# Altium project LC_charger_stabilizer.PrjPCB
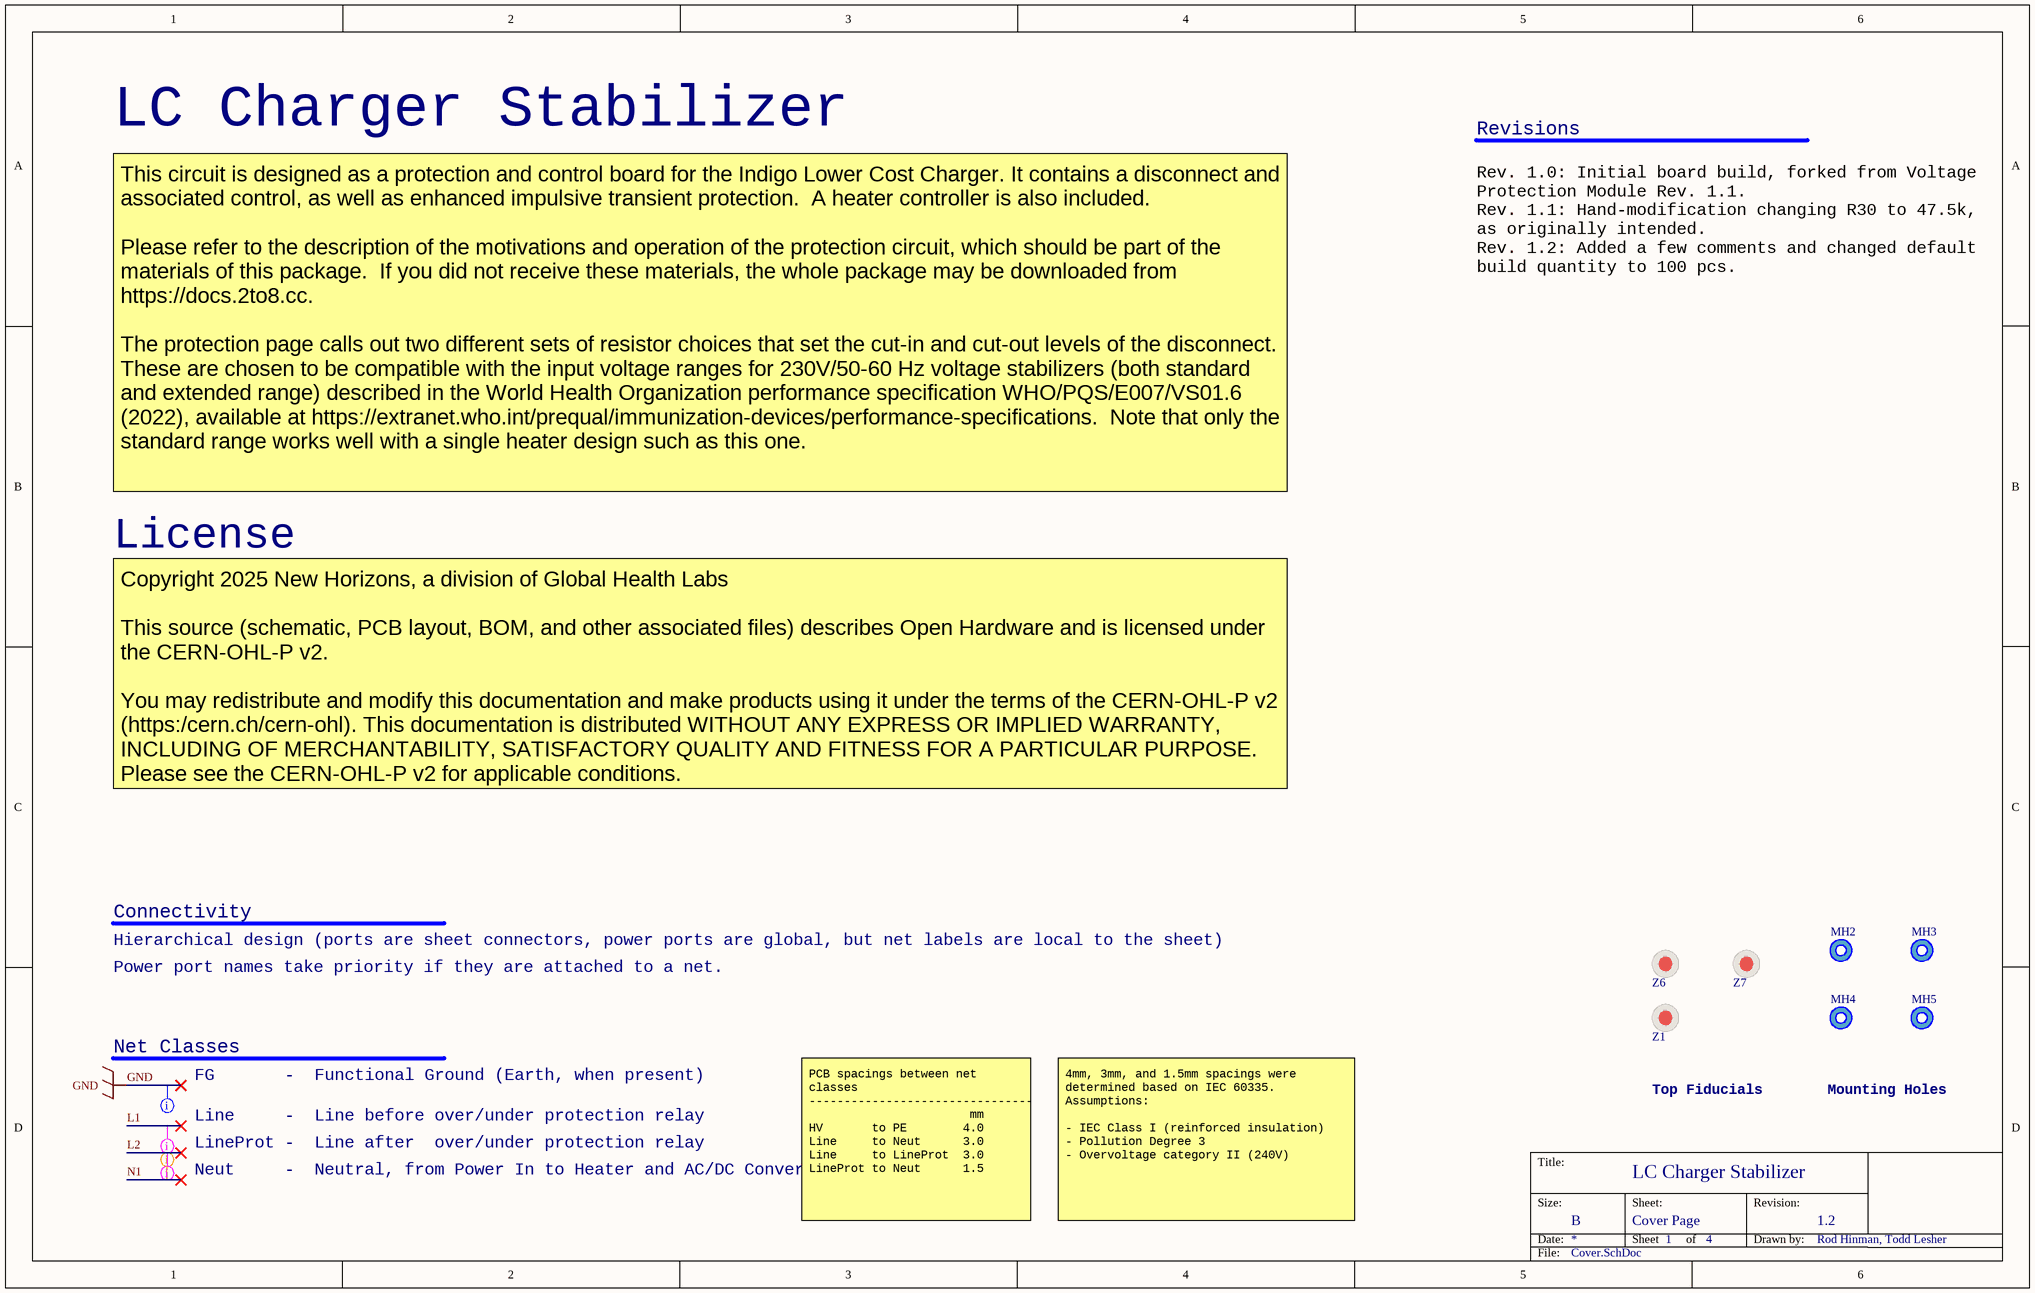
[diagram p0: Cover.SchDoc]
nhToday: 2025-07-28; nhSheetTotal: 4; nhProjRev: 1.2; nhProjName: LC Charger Stabilizer; nhEngPhone: 808-989-0977; nhEngName: Rod Hinman, Todd Lesher; nhEngEmail: rhinman@nhgh.org, rod@auroraresearch.com
5 sheets, 160 parts. Net scope: flat (ports and power ports of the same name join across sheets).
Board file: lc_charger_stab.PcbDoc
Sheets:
  Cover.SchDoc
  PowerHV.SchDoc
  Protect.SchDoc
  HeaterControl.SchDoc
  DebugProbe.SchDoc

## Sheet Cover.SchDoc
size B; SheetNumber: 1; SheetTotal: 4; nhSheetName: Cover Page

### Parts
MH2  MOUNTING_HOLE_3MM_UNPLATED  [MOUNT_HOLE_3MM_NOCOPPER]  (value not drawn)  (no BOM)
MH3  MOUNTING_HOLE_3MM_UNPLATED  [MOUNT_HOLE_3MM_NOCOPPER]  (value not drawn)  (no BOM)
MH4  MOUNTING_HOLE_3MM_UNPLATED  [MOUNT_HOLE_3MM_NOCOPPER]  (value not drawn)  (no BOM)
MH5  MOUNTING_HOLE_3MM_UNPLATED  [MOUNT_HOLE_3MM_NOCOPPER]  (value not drawn)  (no BOM)
Z1  FIDUCIAL_1_3  [FIDUCIAL_1_3_KEEPOUT]  (value not drawn)  (no BOM)
Z6  FIDUCIAL_1_3  [FIDUCIAL_1_3_KEEPOUT]  (value not drawn)  (no BOM)
Z7  FIDUCIAL_1_3  [FIDUCIAL_1_3_KEEPOUT]  (value not drawn)  (no BOM)

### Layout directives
net class Neut: N1
net class Line: L1
net class LineProt: L2
net class FG: GND

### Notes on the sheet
- LC Charger Stabilizer
- Revisions
- Rev. 1.0: Initial board build, forked from Voltage Protection Module Rev. 1.1.
  Rev. 1.1: Hand-modification changing R30 to 47.5k, as originally intended.
  Rev. 1.2: Added a few comments and changed default build quantity to 100 pcs.
- This circuit is designed as a protection and control board for the Indigo Lower Cost Charger. It contains a disconnect and associated control, as well as enhanced impulsive transient protection.  A heater controller is also included.
  Please refer to the description of the motivations and operation of the protection circuit, which should be part of the materials of this package.  If you did not receive these materials, the whole package may be downloaded from https://docs.2to8.cc.
  The protection page calls out two different sets of resistor choices that set the cut-in and cut-out levels of the disconnect.  These are chosen to be compatible with the input voltage ranges for 230V/50-60 Hz voltage stabilizers (both standard and extended range) described in the World Health Organization performance specification WHO/PQS/E007/VS01.6 (2022), available at https://extranet.who.int/prequal/immunization-devices/performance-specifications.  Note that only the standard range works well with a single heater design such as this one.
- License
- Copyright 2025 New Horizons, a division of Global Health Labs
  This source (schematic, PCB layout, BOM, and other associated files) describes Open Hardware and is licensed under the CERN-OHL-P v2.
  You may redistribute and modify this documentation and make products using it under the terms of the CERN-OHL-P v2 (https:/cern.ch/cern-ohl). This documentation is distributed WITHOUT ANY EXPRESS OR IMPLIED WARRANTY, INCLUDING OF MERCHANTABILITY, SATISFACTORY QUALITY AND FITNESS FOR A PARTICULAR PURPOSE. Please see the CERN-OHL-P v2 for applicable conditions.
- Hierarchical design (ports are sheet connectors, power ports are global, but net labels are local to the sheet)
- Power port names take priority if they are attached to a net.
- Connectivity
- Net Classes
- FG       -  Functional Ground (Earth, when present)
- Top Fiducials
- Mounting Holes
- Neut     -  Neutral, from Power In to Heater and AC/DC Converter
- Line     -  Line before over/under protection relay
- LineProt -  Line after  over/under protection relay
- PCB spacings between net classes
  --------------------------------
  mm
  HV       to PE        4.0
  Line     to Neut      3.0
  Line     to LineProt  3.0
  LineProt to Neut      1.5
- 4mm, 3mm, and 1.5mm spacings were determined based on IEC 60335.
  Assumptions:
  - IEC Class I (reinforced insulation)
  - Pollution Degree 3
  - Overvoltage category II (240V)

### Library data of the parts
MH2-MH5 = CMP-NOBOM-00004-3: Hole for M3 screw, unplated
Z1 Z6 Z7 = CMP-NOBOM-00000-13: Fiducial 1 mm copper, 3 mm solder mask, two footprint options.

## Sheet PowerHV.SchDoc
size B; SheetNumber: 2; SheetTotal: 4; nhSheetName: HV Power
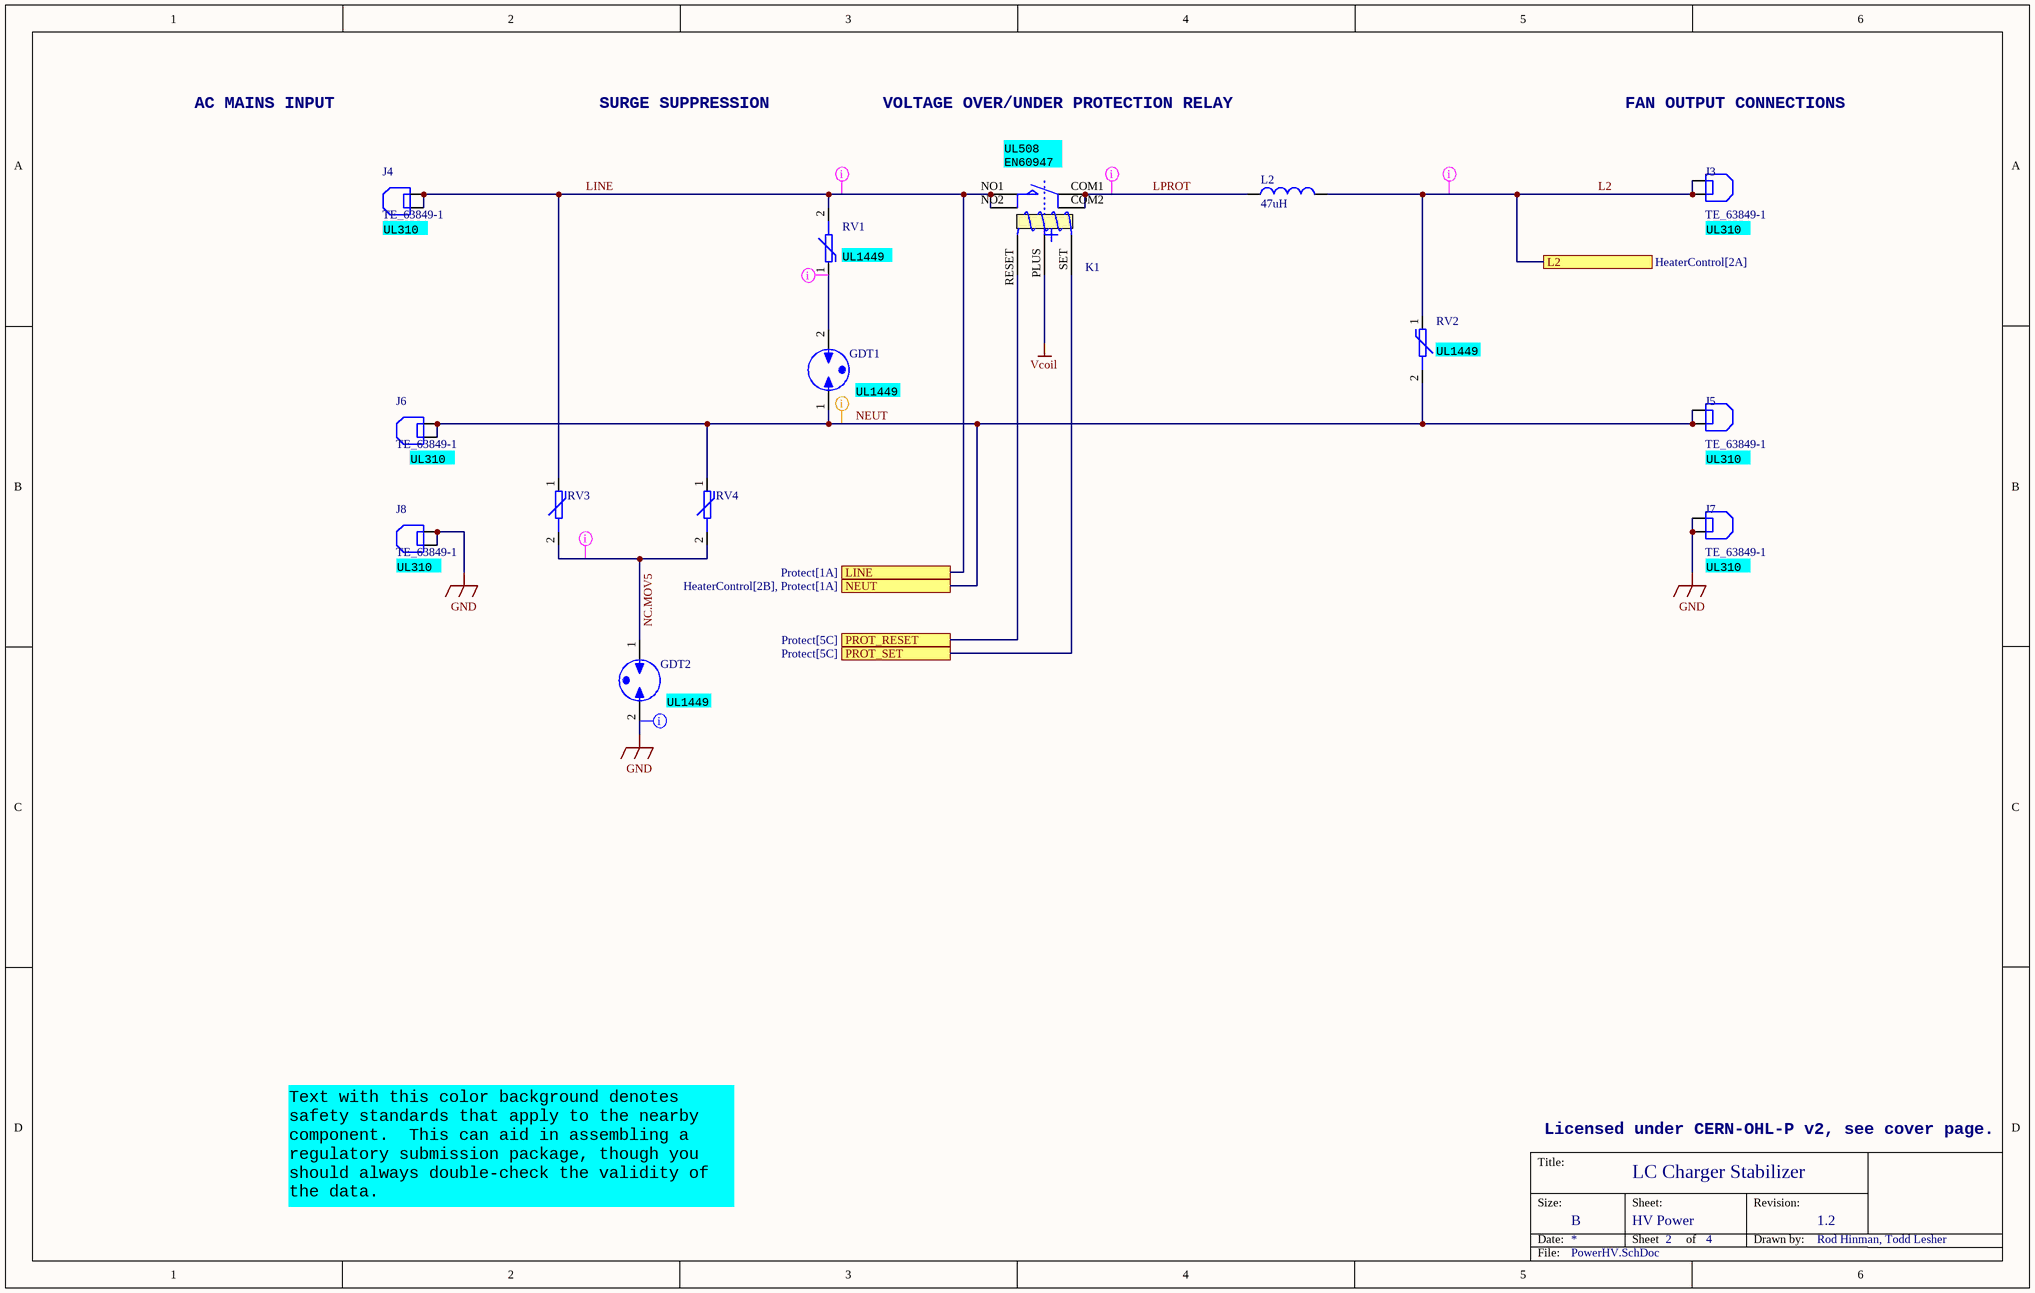
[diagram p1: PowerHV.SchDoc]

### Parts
GDT1  CG31.0L  [LITTELFUSE_CG3x]  (value not drawn)
GDT2  CG32.5L  [LITTELFUSE_CG3x]  (value not drawn)
J3  TE_63849-1  [AMP_63849-1]
J4  TE_63849-1  [AMP_63849-1]
J5  TE_63849-1  [AMP_63849-1]
J6  TE_63849-1  [AMP_63849-1]
J7  TE_63849-1  [AMP_63849-1]
J8  TE_63849-1  [AMP_63849-1]
K1  TE_CONN_2-1415898-5  [TE_RT1_2COIL_LATCHING]  (value not drawn)
L2  value 47uH  [BELFUSE_HCTI_TOROIDAL_INDUCTOR]  (hidden comment: BELFUSE_HCTI-47-10.7)
RV1  TMOV20RP300E  [MOV_RAD7.5P5.5S_DISC_20X11.5]  (value not drawn)
RV2  TMOV20RP300E  [MOV_RAD7.5P5.5S_DISC_20X11.5]  (value not drawn)
RV3  TMOV20RP300E  [MOV_RAD7.5P5.5S_DISC_20X11.5]  (value not drawn)
RV4  TMOV20RP300E  [MOV_RAD7.5P5.5S_DISC_20X11.5]  (value not drawn)

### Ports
L2 (see HeaterControl[2A]), LINE (see Protect[1A]), NEUT (see HeaterControl[2B], Protect[1A]), PROT_RESET (see Protect[5C]), PROT_SET (see Protect[5C])

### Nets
GND: GDT2.2 J7.1 J7.2 J8.1 J8.2
Vcoil: K1.PLUS
L2: J3.1 J3.2 L2.2 RV2.1 ; port L2
LINE: J4.1 J4.2 K1.NO1 K1.NO2 RV1.2 RV3.1 ; port LINE
LPROT: K1.COM1 K1.COM2 L2.1
NC.MOV5: GDT2.1 RV3.2 RV4.2
NEUT: GDT1.1 J5.1 J5.2 J6.1 J6.2 RV2.2 RV4.1 ; port NEUT
PROT_RESET: K1.RESET ; port PROT_RESET
PROT_SET: K1.SET ; port PROT_SET
NetGDT1_2: GDT1.2 RV1.1

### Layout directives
net class Line: LINE, NC.MOV5, NetGDT1_2
net class LineProt: L2, LPROT
net class Neut: NEUT
net class FG: GND

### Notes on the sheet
- AC MAINS INPUT
- SURGE SUPPRESSION
- VOLTAGE OVER/UNDER PROTECTION RELAY
- (near K1) UL508
  EN60947
- FAN OUTPUT CONNECTIONS
- (near J4) UL310
- (near J3) UL310
- (near RV1) UL1449
- (near RV2) UL1449
- (near GDT1) UL1449
- (near J6) UL310
- (near J5) UL310
- (near J8) UL310
- (near J7) UL310
- (near GDT2) UL1449
- Licensed under CERN-OHL-P v2, see cover page.
- Text with this color background denotes safety standards that apply to the nearby component.  This can aid in assembling a regulatory submission package, though you should always double-check the validity of the data.

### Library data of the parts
GDT1 = CMP-PROT-00004-3: CG3 Series - Two Terminal High Voltage Gas Plasma Arresters, 1000V, 10kA, plug in, RoHS; Breakdown Voltage: 1.0kV
GDT2 = CMP-PROT-00003-4: Arrestor; 2500 V (min.) (breakdown); Rugged Ceramic-metal Package; 1 Pf (max.); Breakdown Voltage: 2.5kV
J3-J8 = CMP-CONN-00004-5: Quick Disconnect Terminal 12-24AWG Brass Tab 14.02mm Tin Over Copper/Tin Over Nickel Bag; Tab Width: 6.35mm
K1 = CMP-RELAY-00000-5: Electromechanical Relay SPST-NO 16A 12VDC 240Ohm Through Hole; Contact Voltage Rating (AC): 250V; Coil Power: 600mW; Throw Configuration: SPST
L2 = CMP-IND-00005-4: 47 µH Shielded Toroidal Inductor 10.7 A 16mOhm Max Radial, Vertical (Open); Tolerance: 15%; DC Resistance (DCR): 16mR; Core Material: Ferrite; Current Rating: 10.7A
RV1 RV3 RV4 = CMP-PROT-00005-4: Thermally Protected Varistor 300 V RMS 775 V Clamp 10000 A 800 pF Radial Lead; Voltage Rating (AC): 300V; Varistor Voltage: 517V
RV2 = CMP-PROT-00005-4: Thermally Protected Varistor 300 V RMS 775 V Clamp 10000 A 800 pF Radial Lead; Varistor Voltage: 517V; Voltage Rating (AC): 300V

## Sheet Protect.SchDoc
size B; SheetNumber: 3; SheetTotal: 4; nhSheetName: Protect
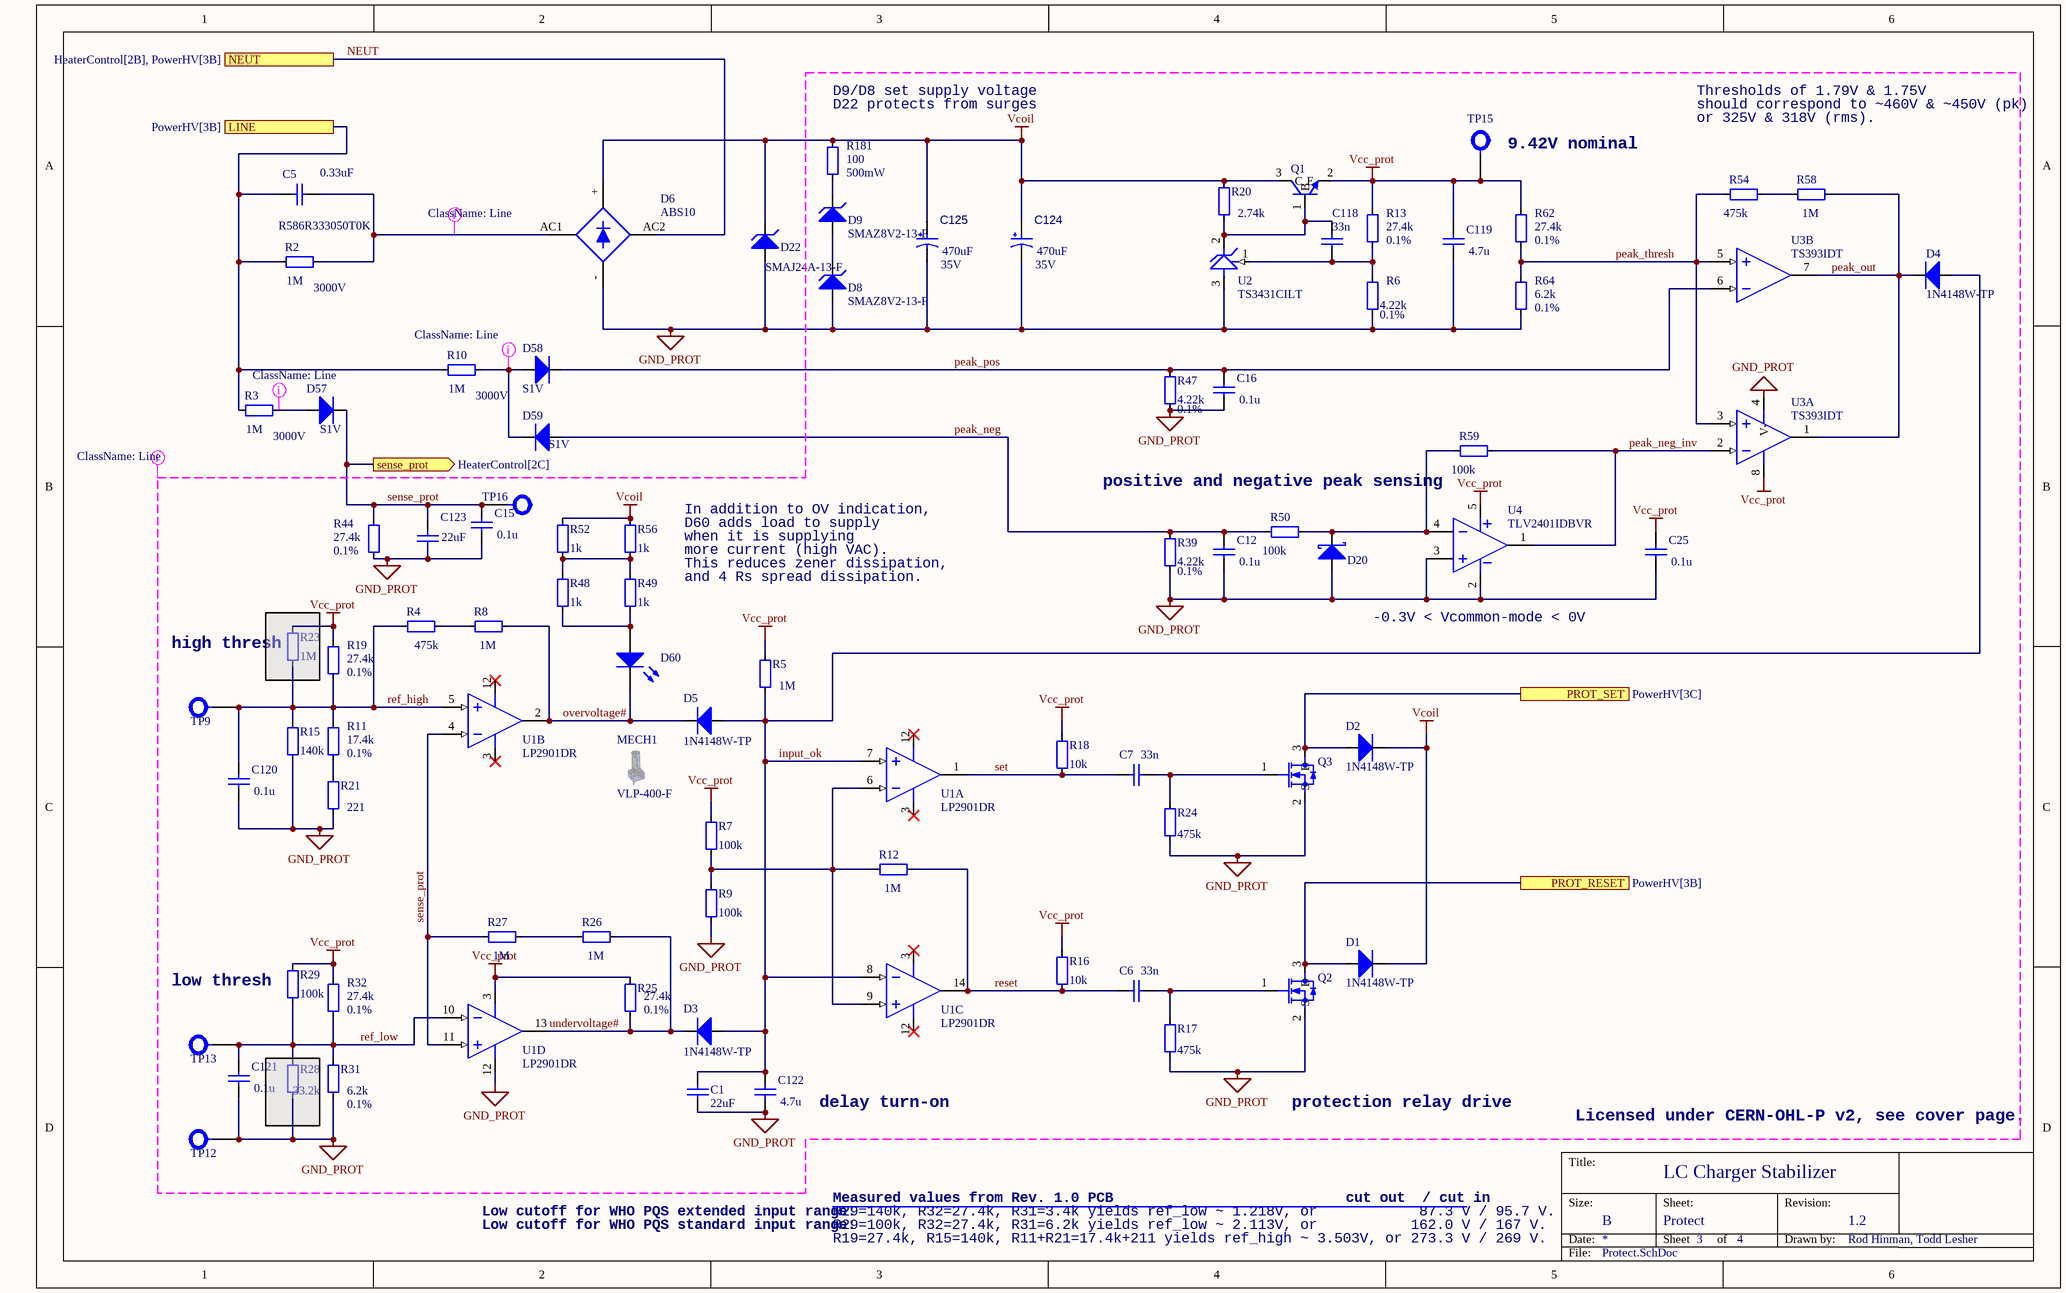
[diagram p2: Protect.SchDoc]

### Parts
C1  value 22uF  [CAPC2012X135,0805,]  (hidden comment: CL21A226MOCLRNC)
C5  R586R333050T0K  value 0.33uF  [CAP_RAD28P3213X22]
C6  value 33n  [CAPC1608X09N,0603,]  (hidden comment: CL10B333KB8NNNC)
C7  value 33n  [CAPC1608X09N,0603,]  (hidden comment: CL10B333KB8NNNC)
C12  value 0.1u  [CAPC1608X09N,0603,]  (hidden comment: CL10B104KB8NNNL)
C15  value 0.1u  [CAPC1608X09N,0603,]  (hidden comment: CL10B104KB8NNNL)
C16  value 0.1u  [CAPC1608X09N,0603,]  (hidden comment: CL10B104KB8NNNL)
C25  value 0.1u  [CAPC1608X09N,0603,]  (hidden comment: CL10B104KB8NNNL)
C118  value 33n  [CAPC1608X09N,0603,]  (hidden comment: CL10B333KB8NNNC)
C119  value 4.7u  [CAPC1608X09N,0603,]  (hidden comment: CL10A475KA8NQNC)
C120  value 0.1u  [CAPC1608X09N,0603,]  (hidden comment: CL10B104KB8NNNL)
C121  value 0.1u  [CAPC1608X09N,0603,]  (hidden comment: CL10B104KB8NNNL)
C122  value 4.7u  [CAPC1608X09N,0603,]  (hidden comment: CL10A475KA8NQNC)
C123  value 22uF  [CAPC2012X135,0805,]  (hidden comment: CL21A226MOCLRNC)
C124  value 470uF  Voltage Rating (DC): 35V  [CAP_RAD5P_CYL_10X20]  (hidden comment: ESH477M035AH3AA)
C125  value 470uF  Voltage Rating (DC): 35V  [CAP_RAD5P_CYL_10X20]  (hidden comment: ESH477M035AH3AA)
D1  1N4148W-TP  [SOD-123]
D2  1N4148W-TP  [SOD-123]
D3  1N4148W-TP  [SOD-123]
D4  1N4148W-TP  [SOD-123]
D5  1N4148W-TP  [SOD-123]
D6  ABS10  [SOP400P640X170-4N_BRIDGE]
D8  SMAZ8V2-13-F  [DO-214AC]
D9  SMAZ8V2-13-F  [DO-214AC]
D20  MBR130T1G  [SOD-123]  (value not drawn)
D22  SMAJ24A-13-F  [DO-214AC]
D57  S1V  [DO-214AC]
D58  S1V  [DO-214AC]
D59  S1V  [DO-214AC]
D60  APTR3216SURCK  [LEDC3216X08NREDBOT,1206,]  (value not drawn)
MECH1  VLP-400-F  [BIVAR_VLP-400-F]
Q1  BCV72,215  [SOT95P275X125-3N]  (value not drawn)
Q2  IRLML6346TRPBF  [SOT95P275X125-3N]  (value not drawn)
Q3  IRLML6346TRPBF  [SOT95P275X125-3N]  (value not drawn)
R2  value 1M  Voltage Rating: 3000V  [RESC6534X70,2512,]  (hidden comment: CHV2512-FX-1004ELF)
R3  value 1M  Voltage Rating: 3000V  [RESC6534X70,2512,]  (hidden comment: CHV2512-FX-1004ELF)
R4  value 475k  [RESC1608X05AN,0603,]  (hidden comment: ERJ-3EKF4753V)
R5  value 1M  [RESC1608X05AN,0603,]  (hidden comment: ERJ-3EKF1004V)
R6  value 4.22k  Tolerance: 0.1%  [RESC1608X05AN,0603,]  (hidden comment: ERA-3AEB4221V)
R7  value 100k  [RESC1608X05AN,0603,]  (hidden comment: ERJ-3EKF1003V)
R8  value 1M  [RESC1608X05AN,0603,]  (hidden comment: ERJ-3EKF1004V)
R9  value 100k  [RESC1608X05AN,0603,]  (hidden comment: ERJ-3EKF1003V)
R10  value 1M  Voltage Rating: 3000V  [RESC6534X70,2512,]  (hidden comment: CHV2512-FX-1004ELF)
R11  value 17.4k  Tolerance: 0.1%  [RESC1608X05AN,0603,]  (hidden comment: ERA-3AEB1742V)
R12  value 1M  [RESC1608X05AN,0603,]  (hidden comment: ERJ-3EKF1004V)
R13  value 27.4k  Tolerance: 0.1%  [RESC1608X05AN,0603,]  (hidden comment: ERA-3AEB2742V)
R15  value 140k  [RESC1608X05AN,0603,]  (hidden comment: RMCF0603FT140K)
R16  value 10k  [RESC1608X05AN[0603]]  (hidden comment: RMCF0603FT10K0)
R17  value 475k  [RESC1608X05AN,0603,]  (hidden comment: ERJ-3EKF4753V)
R18  value 10k  [RESC1608X05AN[0603]]  (hidden comment: RMCF0603FT10K0)
R19  value 27.4k  Tolerance: 0.1%  [RESC1608X05AN,0603,]  (hidden comment: ERA-3AEB2742V)
R20  value 2.74k  [RESC1608X05AN,0603,]  (hidden comment: RMCF0603FT2K74)
R21  value 221  [RESC1608X05AN,0603,]  (hidden comment: ERJ-3EKF2210V)
R23  value 1M  [RESC1608X05AN,0603,]  (hidden comment: ERJ-3EKF1004V)
R24  value 475k  [RESC1608X05AN,0603,]  (hidden comment: ERJ-3EKF4753V)
R25  value 27.4k  Tolerance: 0.1%  [RESC1608X05AN,0603,]  (hidden comment: ERA-3AEB2742V)
R26  value 1M  [RESC1608X05AN,0603,]  (hidden comment: ERJ-3EKF1004V)
R27  value 1M  [RESC1608X05AN,0603,]  (hidden comment: ERJ-3EKF1004V)
R28  value 33.2k  [RESC1608X05AN,0603,]  (hidden comment: ERJ-3EKF3322V)
R29  value 100k  [RESC1608X05AN,0603,]  (hidden comment: ERJ-3EKF1003V)
R31  value 6.2k  Tolerance: 0.1%  [RESC1608X05AN,0603,]  (hidden comment: ERA-3AEB622V)
R32  value 27.4k  Tolerance: 0.1%  [RESC1608X05AN,0603,]  (hidden comment: ERA-3AEB2742V)
R39  value 4.22k  Tolerance: 0.1%  [RESC1608X05AN,0603,]  (hidden comment: ERA-3AEB4221V)
R44  value 27.4k  Tolerance: 0.1%  [RESC1608X05AN,0603,]  (hidden comment: ERA-3AEB2742V)
R47  value 4.22k  Tolerance: 0.1%  [RESC1608X05AN,0603,]  (hidden comment: ERA-3AEB4221V)
R48  value 1k  [RESC1608X05AN,0603,]  (hidden comment: ERJ-3EKF1001V)
R49  value 1k  [RESC1608X05AN,0603,]  (hidden comment: ERJ-3EKF1001V)
R50  value 100k  [RESC1608X05AN,0603,]  (hidden comment: ERJ-3EKF1003V)
R52  value 1k  [RESC1608X05AN,0603,]  (hidden comment: ERJ-3EKF1001V)
R54  value 475k  [RESC1608X05AN,0603,]  (hidden comment: ERJ-3EKF4753V)
R56  value 1k  [RESC1608X05AN,0603,]  (hidden comment: ERJ-3EKF1001V)
R58  value 1M  [RESC1608X05AN,0603,]  (hidden comment: ERJ-3EKF1004V)
R59  value 100k  [RESC1608X05AN,0603,]  (hidden comment: ERJ-3EKF1003V)
R62  value 27.4k  Tolerance: 0.1%  [RESC1608X05AN,0603,]  (hidden comment: ERA-3AEB2742V)
R64  value 6.2k  Tolerance: 0.1%  [RESC1608X05AN,0603,]  (hidden comment: ERA-3AEB622V)
R181  value 100  Power: 500mW  [RESC2012X06N,0805,]  (hidden comment: ERJ-P06F1000V)
TP9  TP TH  0.78mm  [TP_TH078H127P]  (value not drawn)  (no BOM)
TP12  TP TH  0.78mm  [TP_TH078H127P]  (value not drawn)  (no BOM)
TP13  TP TH  0.78mm  [TP_TH078H127P]  (value not drawn)  (no BOM)
TP15  TP TH  0.78mm  [TP_TH078H127P]  (value not drawn)  (no BOM)
TP16  TP TH  0.78mm  [TP_TH078H127P]  (value not drawn)  (no BOM)
U1  LP2901DR  [SOIC127P600X175-14N]  (parts A,B,C,D of 4)
U2  TS3431CILT  [SOT95P275X125-3N]
U3  TS393IDT  [SOIC127P600X175-8N]  (parts A,B of 2)
U4  TLV2401IDBVR  [SOT95P280X145-5N]

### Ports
LINE (see PowerHV[3B]), NEUT (see HeaterControl[2B], PowerHV[3B]), PROT_RESET (see PowerHV[3B]), PROT_SET (see PowerHV[3C]), sense_prot (out, see HeaterControl[2C])

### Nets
GND_PROT: C1.2 C12.2 C15.2 C16.2 C25.2 C119.2 C120.2 C121.2 C122.2 C123.2 C124.- C125.- D6.- D8.A D20.A D22.A Q2.2(S) Q3.2(S) R6.2 R9.2 R15.2 R17.1 R21.2 R24.1 R28.2 R31.2 R39.2 R44.2 R47.2 R64.2 TP12.1 U1.12(V-) U2.3(A) U3.4(V-) U4.2(-Vs) U4.3(+IN)
Vcc_prot: C25.1 C119.1 Q1.2(E) R5.1 R7.1 R13.1 R16.1 R18.1 R19.1 R23.1 R25.2 R29.1 R32.1 R62.1 TP15.1 U1.3(V+) U3.8(V+) U4.5(+Vs)
Vcoil: C124.+ C125.+ D1.K D2.K D6.+ D22.K Q1.3(C) R20.2 R52.1 R56.1 R181.1
input_ok: C1.1 C122.1 D3.A D4.A D5.A R5.2 U1.7(IN1+) U1.8(IN3-)
LINE: C5.1 R2.1 R3.1 R10.1 ; port LINE
NEUT: D6.AC2 ; port NEUT
overvoltage#: D5.K D60.K R8.2 U1.2(OUT2)
peak_neg: C12.1 D59.A R39.1 R50.1
peak_neg_inv: R59.2 U3.2(IN1-) U4.1(OUT)
peak_out: D4.K R58.2 U3.1(OUT1) U3.7(OUT2)
peak_pos: C16.1 D58.K R47.1 U3.6(IN2-)
peak_thresh: R54.2 R62.2 R64.1 U3.3(IN1+) U3.5(IN2+)
PROT_RESET: D1.A Q2.3(D) ; port PROT_RESET
PROT_SET: D2.A Q3.3(D) ; port PROT_SET
ref_high: C120.1 R4.2 R11.2 R15.1 R19.2 R23.2 TP9.1 U1.5(IN2+)
ref_low: C121.1 R28.1 R29.2 R31.1 R32.2 TP13.1 U1.10(IN4-)
reset: C6.1 R12.2 R16.2 U1.14(OUT3)
sense_prot: C15.1 C123.1 D57.K R27.1 R44.1 TP16.1 U1.4(IN2-) U1.11(IN4+) ; port sense_prot
set: C7.1 R18.2 U1.1(OUT1)
undervoltage#: D3.K R25.1 R26.2 U1.13(OUT4)
NetC5_2: C5.2 D6.AC1 R2.2
NetC6_2: C6.2 Q2.1(G) R17.2
NetC7_2: C7.2 Q3.1(G) R24.2
NetC118_1: C118.1 Q1.1(B) R20.1 U2.2(K)
NetC118_2: C118.2 R6.1 R13.2 U2.1(VREF)
NetD8_K: D8.K D9.A
NetD9_K: D9.K R181.2
NetD20_K: D20.K R50.2 R59.1 U4.4(-IN)
NetD57_A: D57.A R3.2
NetD58_A: D58.A D59.K R10.2
NetD60_A: D60.A R48.2 R49.2
NetR4_1: R4.1 R8.1
NetR7_2: R7.2 R9.1 R12.1 U1.6(IN1-) U1.9(IN3+)
NetR11_1: R11.1 R21.1
NetR26_1: R26.1 R27.2
NetR48_1: R48.1 R49.1 R52.2 R56.2
NetR54_1: R54.1 R58.1

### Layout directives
net class Line: GND_PROT, input_ok, NetC5_2, NetD57_A, NetD58_A, overvoltage#, peak_neg, peak_neg_inv, peak_out, peak_pos, peak_thresh, ref_high, ref_low, reset, sense_prot, set, undervoltage#, Vcc_prot, Vcoil

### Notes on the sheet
- (near R181) D9/D8 set supply voltage
- Thresholds of 1.79V & 1.75V
- (near R181) D22 protects from surges
- (near TP15) 9.42V nominal
- should correspond to ~460V & ~450V (pk)
- or 325V & 318V (rms).
- positive and negative peak sensing
- D60 adds load to supply
- when it is supplying
- more current (high VAC).
- This reduces zener dissipation,
- In addition to OV indication,
- and 4 Rs spread dissipation.
- (near U4) -0.3V < Vcommon-mode < 0V
- (near R23) high thresh
- low thresh
- delay turn-on
- protection relay drive
- Licensed under CERN-OHL-P v2, see cover page.
- Low cutoff for WHO PQS extended input range:
- Low cutoff for WHO PQS standard input range:
- R29=140k, R32=27.4k, R31=3.4k yields ref_low ~ 1.218V, or            87.3 V / 95.7 V.
- R19=27.4k, R15=140k, R11+R21=17.4k+211 yields ref_high ~ 3.503V, or 273.3 V / 269 V.
- Measured values from Rev. 1.0 PCB
- R29=100k, R32=27.4k, R31=6.2k yields ref_low ~ 2.113V, or           162.0 V / 167 V.
- cut out  / cut in

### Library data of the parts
C1 C123 = CMP-CAP-00014-5: Multilayer Ceramic Capacitor, 22 uF, 16 V, ± 20%, X5R, 0805 [2012 Metric]; Voltage: 16V
C5 = CMP-CAP-00013-4: CAP FILM 600VAC(X1) 0.33 UF 10%
C6 C7 C118 = CMP-CAP-00006-11: Multilayer Ceramic Capacitor, 0.033 uF, 50 V, ± 10%, X7R, 0603 [1608 Metric]; Voltage Rating: 50V
C12 C15 C16 C25 C120 C121 = CMP-CAP-00002-13: Multilayer Ceramic Capacitor, 0.1 uF, 50 V, ± 10%, X7R, 0603 [1608 Metric]; Voltage Rating: 50V; Material: 4241
C119 C122 = CMP-CAP-00007-11: Multilayer Ceramic Capacitor, 4.7 uF, 25 V, ± 10%, X5R, 0603 [1608 Metric]; Voltage Rating: 25V; Dielectric: X7R
C124 C125 = CMP-CAP-00011-4: Capacitor; Al Electrolytic; Cap 470 uF; Tol 20%; Vol-Rtg 35 VDC; Radial; 10x17 mm; Dissipation Factor: 0.14%; Life (Hours): 2000Hour
D1-D5 = CMP-DIO-00000-5: Rectifier Diode Switching 100V 0.3A 4ns 2-Pin SOD-123 T/R / DIODE GEN PURP 100V 150MA SOD123; Forward Voltage: 1V; Power Dissipation: 400mW
D6 = CMP-DIO-00006-4: Bridge Rectifier Abs/Sopa-4 T&r 5K Rohs Compliant: Yes
D8 D9 = CMP-DIO-00003-5: DIODE ZENER 8.2V 1W SMA; Reverse Recovery Time: 1.8us; Forward Current: 1A; Forward Voltage: 1.2V
D20 = CMP-DIO-00001-5: DIODE SCHOTTKY 30V 1A SOD123 / Rectifier Diode Schottky 30V 1A 2-Pin SOD-123 T/R; Power Dissipation: 400mW; Reverse Recovery Time: 4ns; Forward Voltage: 470mV
D22 = CMP-DIO-00004-5: SMAJ24A Series 400 W 24 V Surface Mount Uni-Directional TVS Diode - DO-214AC; Forward Current: 1A; Power Dissipation: 400W; Forward Voltage: 1.2V; Reverse Recovery Time: 1.8us; Voltage Rating (DC): 24V
D57-D59 = CMP-DIO-00007-4: Diode Rectifier 2000V 1A 2-Pin DO-214AC T/R; Reverse Recovery Time: 2.5us; Forward Voltage: 1V; Voltage Rating (DC): 2kV; Power Dissipation: 1.4W
D60 = CMP-LED-00004-3: Red 3.2 x 1.6 x 1.05 mm (1206) 120º Water Clear 150 mcd 1.95 V Chip LED Lamp SMT; Forward Voltage: 1.95V; Forward Current: 20mA; Viewing Angle: 120°
MECH1 = CMP-LED-00003-7: Light Pipe, Rigid, Vertical, Board Mount, SMD LED, .400 in., Flat Face
Q1 = CMP-BJT-00000-3: BCV72 Series 60 V 100 mA 250 mW NPN SMT General Purpose Transistor - SOT-23; Collector Emitter Voltage (VCEO): 60V; Collector Base Voltage (VCBO): 80V; Frequency: 100MHz; Max Collector Current: 100mA
Q2 Q3 = CMP-FET-00000-3: MOSFET Transistor, N Channel, 3.4 A, 30 V, 0.046 ohm, 4.5 V, 800 mV; Drain to Source Voltage (Vdss): 30V; Continuous Drain Current (ID): 3.4A; Drain to Source Resistance: 46mR
R2 R3 R10 = CMP-RES-00067-6: SMD Chip Resistor, 1 MOhm, ± 1%, 1 W, 2512 [6332 Metric], Thick Film, High Voltage; Max Power Dissipation: 1.0W; Temperature Coefficient: 100ppm/°C
R4 R17 R24 R54 = CMP-RES-00002-10: SMD Chip Resistor, 475 kOhm, ± 1%, 100 mW, 0603 [1608 Metric], Thick Film, Precision; Max Power Dissipation: 100mW; Voltage Rating: 75V; Temperature Coefficient: 100ppm/°C
R5 R8 R12 R23 R26 R27 R58 = CMP-RES-00000-13: Res Thick Film 0603 1M Ohm 1% 1/10W ±100ppm/°C Molded SMD Punched Carrier T/R; Voltage Rating (DC): 75V; Max Power Dissipation: 100mW
R6 R39 R47 = CMP-RES-00064-10: Res Thin Film 0603 4.22K Ohm 0.1% 1/10W ±25ppm/°C Molded SMD SMD Punched Carrier T/R; Max Power Dissipation: 100mW; Voltage Rating: 75V
R7 R9 R50 R59 = CMP-RES-00004-12: Resistor Thick Film 0603 100K Ohm 1% 1/10W 100ppm/C Molded SMD Punched Carrier T/R; Max Power Dissipation: 100mW; Voltage Rating (DC): 75V; Temperature Coefficient: 100ppm/°C
R11 = CMP-RES-00063-10: Res Thin Film 0603 17.4K Ohm 0.1% 0.1W(1/10W) ±25ppm/C Pad SMD Automotive T/R; Max Power Dissipation: 100mW; Voltage Rating (DC): 75V; Temperature Coefficient: 25ppm/°C
R13 R19 R25 R32 R44 R62 = CMP-RES-00062-10: Res Thin Film 0603 27.4K Ohm 0.1% 0.1W(1/10W) ±25ppm/C Pad SMD Automotive T/R; Power: 100mW; Temperature Coefficient: 25ppm/°C; Voltage Rating: 75V
R15 = CMP-RES-00060-10: Res Thick Film 0603 140K Ohm 1% 1/10W ±100ppm/°C Molded SMD SMD Paper T/R; Voltage Rating (DC): 75V; Power: 100mW
R16 R18 = CMP-RES-00016-12: Res Thick Film 0603 10K Ohm 1% 1/10W ±100ppm/°C Molded SMD SMD Paper T/R; Max Power Dissipation: 100mW; Voltage Rating (DC): 75V
R20 = CMP-RES-00061-10: Res Thick Film 0603 2.74K Ohm 1% 1/10W ±100ppm/°C Molded SMD SMD Paper T/R; Voltage Rating: 75V; Power Rating: 100mW
R21 = CMP-RES-00012-10: SMD Chip Resistor, 221 Ohm, ± 1%, 100 mW, 0603 [1608 Metric], Thick Film, Precision; Temperature Coefficient: 100ppm/°C; Voltage Rating: 75V; Power Rating: 100mW
R28 = CMP-RES-00008-10: Res Thick Film 0603 33.2K Ohm 1% 1/10W +/-100ppm/ßC Molded SMD Punched Carrier T/R; Voltage Rating: 50V; Power: 100mW; Temperature Coefficient: 100ppm/°C
R29 = CMP-RES-00004-12: Resistor Thick Film 0603 100K Ohm 1% 1/10W 100ppm/C Molded SMD Punched Carrier T/R; Voltage Rating (DC): 75V; Power: 100mW; Temperature Coefficient: 100ppm/°C
R31 = CMP-RES-00066-10: Res Thin Film 0603 6.2K Ohm 0.1% 1/10W ±25ppm/°C Molded SMD SMD Punched Carrier T/R; Power: 100mW; Voltage Rating: 75V
R48 R49 R52 R56 = CMP-009-00190-11: Res Thick Film 0603 1K Ohm 1% 1/10W ±100ppm/°C Molded SMD Punched Carrier T/R; Voltage Rating: 75V; Power: 100mW
R64 = CMP-RES-00066-10: Res Thin Film 0603 6.2K Ohm 0.1% 1/10W ±25ppm/°C Molded SMD SMD Punched Carrier T/R; Max Power Dissipation: 100mW; Voltage Rating: 75V
R181 = CMP-RES-00069-5: SMD Chip Resistor, 100 Ohm, ± 1%, 500 mW, 0805 [2012 Metric], Thick Film, Anti-Surge; Temperature Coefficient: 100ppm/°C; Voltage Rating: 150V
TP9 TP12 TP13 TP15 TP16 = NOBOM-00007: Test point, TH, 0.78mm (30mil) hole, 1.27mm (50 mil) pad; manufacturer: New Horizons; id: 137437; reorder_quantity: 0
U1 = CMP-ICANA-00000-3: Quad low-power industrial grade standard comparator 14-SOIC -40 to 85; Min Supply Voltage: 3V; Max Supply Voltage: 30V
U2 = CMP-ICPWR-00000-3: V-Ref Adjustable 1.24V to 24V 100mA 3-Pin SOT-23 T/R; Max Supply Voltage: 25V; Tolerance: 0.25%
U3 = CMP-ICANA-00001-3: Micropower CMOS dual voltage comparator, 9µA, 16V, -40, 0 to 125, 70°C, SO-8, Tape and Reel; Min Supply Voltage: 2.7V
U4 = CMP-ICANA-00002-4: Op Amp Single Low Power Amplifier R-R I/O ±8V/16V 5-Pin SOT-23 T/R; Bandwidth: 5.5kHz; Max Supply Voltage: 16V; Min Supply Voltage: 2.5V

## Sheet HeaterControl.SchDoc
size B; SheetNumber: 4; SheetTotal: 4; nhSheetName: Heater Control
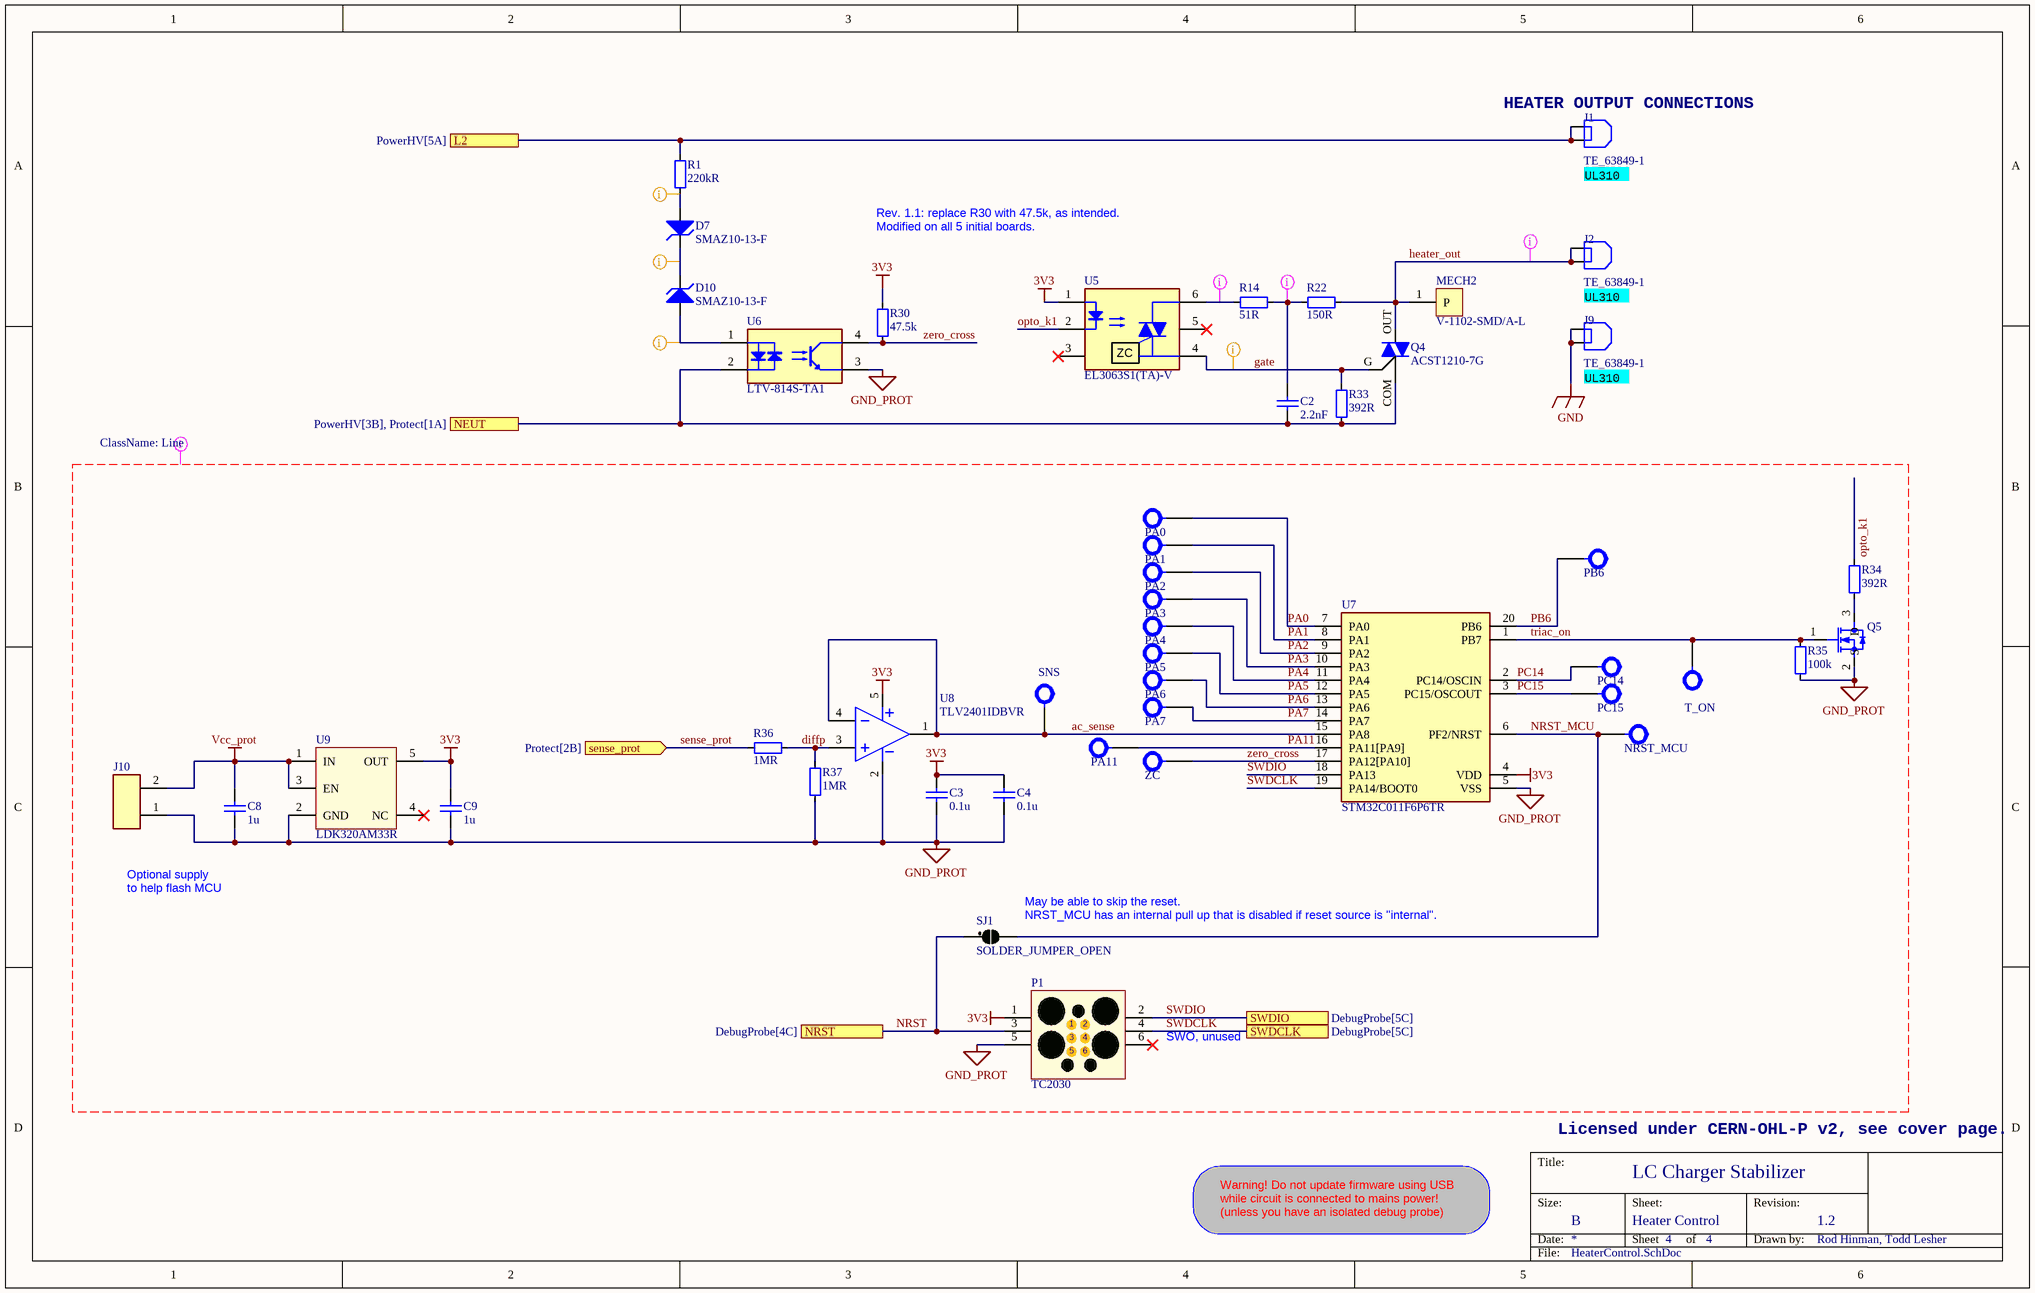
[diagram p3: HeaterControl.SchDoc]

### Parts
C2  value 2.2nF  [CAP_RAD10P1304X09]  (hidden comment: R413F12200000M)
C3  value 0.1u  [CAPC1608X09N,0603,]  (hidden comment: CL10B104KB8NNNL)
C4  value 0.1u  [CAPC1608X09N,0603,]  (hidden comment: CL10B104KB8NNNL)
C8  value 1u  [CAPC1608X09N[0603]]  (hidden comment: CL10B105KA8NFNC)
C9  value 1u  [CAPC1608X09N[0603]]  (hidden comment: CL10B105KA8NFNC)
D7  SMAZ10-13-F  [DO-214AC]
D10  SMAZ10-13-F  [DO-214AC]
J1  TE_63849-1  [AMP_63849-1]
J2  TE_63849-1  [AMP_63849-1]
J9  TE_63849-1  [AMP_63849-1]
J10  22-23-2021  [MOLX-22-23-2021_V]  (value not drawn)
MECH2  V-1102-SMD/A-L  [ASSMANN_V-1102-SMD/A]
NRST_MCU  Test Point 30mil plated  [TP_TH078H127P]  (value not drawn)  (no BOM)
P1  TC2030  [TAG-TC2030-LEGS]  (no BOM)
PA0  Test Point 30mil plated  [TP_TH078H127P]  (value not drawn)  (no BOM)
PA1  Test Point 30mil plated  [TP_TH078H127P]  (value not drawn)  (no BOM)
PA2  Test Point 30mil plated  [TP_TH078H127P]  (value not drawn)  (no BOM)
PA3  Test Point 30mil plated  [TP_TH078H127P]  (value not drawn)  (no BOM)
PA4  Test Point 30mil plated  [TP_TH078H127P]  (value not drawn)  (no BOM)
PA5  Test Point 30mil plated  [TP_TH078H127P]  (value not drawn)  (no BOM)
PA6  Test Point 30mil plated  [TP_TH078H127P]  (value not drawn)  (no BOM)
PA7  Test Point 30mil plated  [TP_TH078H127P]  (value not drawn)  (no BOM)
PA11  Test Point 30mil plated  [TP_TH078H127P]  (value not drawn)  (no BOM)
PB6  Test Point 30mil plated  [TP_TH078H127P]  (value not drawn)  (no BOM)
PC14  Test Point 30mil plated  [TP_TH078H127P]  (value not drawn)  (no BOM)
PC15  Test Point 30mil plated  [TP_TH078H127P]  (value not drawn)  (no BOM)
Q4  ACST1210-7G  [TO-263_TRIAC_N]
Q5  IRLML6346TRPBF  [SOT95P275X125-3N]  (value not drawn)
R1  value 220kR  [RESC5025X60,2010,]  (hidden comment: CHV2010-FX-2203ELF)
R14  value 51R  [RESC3216X70,1206,]  (hidden comment: ERJ-P08J510V)
R22  value 150R  [RESC3216X70,1206,]  (hidden comment: ERJ-P08J151V)
R30  value 47.5k  [RESC1608X05AN,0603,]  (hidden comment: ERJ-3EKF4752V)
R33  value 392R  [RESC1608X05AN,0603,]  (hidden comment: ERJ-3EKF3920V)
R34  value 392R  [RESC1608X05AN,0603,]  (hidden comment: ERJ-3EKF3920V)
R35  value 100k  [RESC1608X05AN,0603,]  (hidden comment: ERJ-3EKF1003V)
R36  value 1MR  [RESC1608X05AN,0603,]  (hidden comment: RT0603BRD071ML)
R37  value 1MR  [RESC1608X05AN,0603,]  (hidden comment: RT0603BRD071ML)
SJ1  SOLDER_JUMPER_OPEN  [SOLDER_JUMPER_OPEN]  (no BOM)
SNS  Test Point 30mil plated  [TP_TH078H127P]  (value not drawn)  (no BOM)
T_ON  Test Point 30mil plated  [TP_TH078H127P]  (value not drawn)  (no BOM)
U5  EL3063S1(TA)-V  [DIP6_SMD_8MM]
U6  LTV-814S-TA1  [DIP4_SMD_8MM]
U7  STM32C011F6P6TR  [TSOP65P640X120-20N]
U8  TLV2401IDBVR  [SOT95P280X145-5N]
U9  LDK320AM33R  [SOT95P280X145-5N]
ZC  Test Point 30mil plated  [TP_TH078H127P]  (value not drawn)  (no BOM)

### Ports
L2 (see PowerHV[5A]), NEUT (see PowerHV[3B], Protect[1A]), NRST (see DebugProbe[4C]), sense_prot (in, see Protect[2B]), SWDCLK (see DebugProbe[5C]), SWDIO (see DebugProbe[5C])

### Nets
3V3: C3.1 C4.1 C9.1 P1.1(VDD) R30.1 U5.1(Anode) U7.4(VDD) U8.5(+Vs) U9.5(OUT)
GND: J9.1 J9.2
GND_PROT: C3.2 C4.2 C8.2 C9.2 J10.1 P1.5(GND) Q5.2(S) R35.2 R37.2 U6.3(Emitter) U7.5(VSS) U8.2(-Vs) U9.2(GND)
Vcc_prot: C8.1 J10.2 U9.1(IN) U9.3(EN)
ac_sense: SNS.1 U7.15(PA8) U8.1(OUT) U8.4(-IN)
diffp: R36.2 R37.1 U8.3(+IN)
gate: Q4.G R33.1 U5.4(Terminal)
heater_out: J2.1 J2.2 MECH2.1(P) Q4.OUT R22.2
L2: J1.1 J1.2 R1.1 ; port L2
NEUT: C2.2 Q4.COM R33.2 U6.2(Cathode) ; port NEUT
NRST: P1.3(~{RESET}) SJ1.1 ; port NRST
NRST_MCU: NRST_MCU.1 SJ1.2 U7.6(PF2/NRST)
opto_k1: R34.1 U5.2(Cathode)
PA0: PA0.1 U7.7(PA0)
PA1: PA1.1 U7.8(PA1)
PA2: PA2.1 U7.9(PA2)
PA3: PA3.1 U7.10(PA3)
PA4: PA4.1 U7.11(PA4)
PA5: PA5.1 U7.12(PA5)
PA6: PA6.1 U7.13(PA6)
PA7: PA7.1 U7.14(PA7)
PA11: PA11.1 U7.16(PA11[PA9])
PB6: PB6.1 U7.20(PB6)
PC14: PC14.1 U7.2(PC14/OSCIN)
PC15: PC15.1 U7.3(PC15/OSCOUT)
sense_prot: R36.1 ; port sense_prot
SWDCLK: P1.4(SWCLK) U7.19(PA14/BOOT0) ; port SWDCLK
SWDIO: P1.2(SWDIO) U7.18(PA13) ; port SWDIO
triac_on: Q5.1(G) R35.1 T_ON.1 U7.1(PB7)
zero_cross: R30.2 U6.4(Collector) U7.17(PA12[PA10]) ZC.1
NetC2_1: C2.1 R14.2 R22.1
NetD7_A: D7.A R1.2
NetD7_K: D7.K D10.K
NetD10_A: D10.A U6.1(Anode)
NetQ5_3: Q5.3(D) R34.2
NetR14_1: R14.1 U5.6(Terminal)

Not connected (* = marked no-connect by the designer): P1 6(SWO)*; U5 3(NC)* 5(NC)*; U9 4(NC)*

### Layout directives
net class Neut: gate, NetD7_A, NetD7_K, NetD10_A
net class Line: 3V3, ac_sense, diffp, GND_PROT, heater_out, NetC2_1, NetR14_1, NRST, NRST_MCU, opto_k1, PA0, PA1, PA2, PA3, PA4, PA5, PA6, PA7, PA11, PB6, PC14, PC15, sense_prot, SWDCLK, SWDIO, triac_on, Vcc_prot, zero_cross

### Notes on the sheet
- (near J1) HEATER OUTPUT CONNECTIONS
- Rev. 1.1: replace R30 with 47.5k, as intended.
- Modified on all 5 initial boards.
- (near J1) UL310
- UL310
- (near J9) UL310
- Optional supply
- to help flash MCU
- (near SJ1) May be able to skip the reset.
- (near SJ1) NRST_MCU has an internal pull up that is disabled if reset source is "internal".
- (near P1) SWO, unused
- Licensed under CERN-OHL-P v2, see cover page.
- Warning! Do not update firmware using USB
- while circuit is connected to mains power!
- (unless you have an isolated debug probe)

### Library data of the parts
C2 = CMP-CAP-00028-3: Film Capacitor, Polypropylene, 1000V, 20% +Tol, 20% -Tol, 0.0022uF, Through Hole Mount; Dielectric: PP; Voltage Rating (DC): 1kV
C3 C4 = CMP-CAP-00002-13: Multilayer Ceramic Capacitor, 0.1 uF, 50 V, ± 10%, X7R, 0603 [1608 Metric]; Material: 4241; Voltage: 50V
C8 C9 = CMP-CAP-00001-13: Ceramic Capacitor, Multilayer, Ceramic, 25V, 10% +Tol, 10% -Tol, X7R, 15% TC, 1uF, Surface Mount, 0603
D7 D10 = CMP-DIO-00011-1: SMAZ10-13 Series 1 W 10 V 200 mA Surface Mount Zener Diode - DO-214AC; Forward Current: 1A; Power Dissipation: 1W; Reverse Recovery Time: 1.8us; Forward Voltage: 1.2V; Value: 10V
J1 J2 J9 = CMP-CONN-00004-5: as J3 on sheet PowerHV
J10 = CMP-CONN-00014-6: KK 254 Solid Header, Vertical, with Friction Lock, 2 Circuits, Tin (Sn) Plating
MECH2 = CMP-THERM-00003-6: Heatsink TO-263 19.38X25.40MM
NRST_MCU PA0-PA7 PA11 PB6 PC14 PC15 SNS T_ON ZC = CMP-NOBOM-00008-2: Test Point plated unpopulated.  30mil hole dia.  50mil copper dia.
P1 = CMP-NOBOM-00012-1: Tag Connect TC2030 with holes for legs
Q4 = CMP-THY-00001-7: Thyristor AC Switch Triac 700V 126A 3-Pin(2+Tab) D2PAK Tube
Q5 = CMP-FET-00000-3: as Q2 on sheet Protect
R1 = CMP-RES-00078-5: SMD Chip Resistor, 220 KOhm, ± 1%, 500 mW, 2010 [5025 Metric], Thick Film, High Voltage; Power: 500mW; Voltage Rating (DC): 3kV; Temperature Coefficient: 100ppm/°C; Power Rating: 1.0W
R14 = CMP-RES-00079-5: Res Thick Film 1206 51 Ohm 5% 0.33W ±200ppm/°C Molded SMD Punched Carrier T/R; Power: 660mW; Max Power Dissipation: 667mW; Voltage Rating: 500V
R22 = CMP-RES-00080-5: Res Thick Film 1206 150 Ohm 5% 1/3W ±200ppm/°C Molded SMD SMD Punched Carrier T/R; Power: 660mW; Voltage Rating: 500V; Max Power Dissipation: 667mW
R30 = CMP-RES-00005-10: Res Thick Film 0603 47.5K Ohm 1% 0.1W(1/10W) ±100ppm/C Pad SMD Automotive T/R; Power: 100mW; Temperature Coefficient: 100ppm/°C; Voltage Rating: 50V
R33 R34 = CMP-RES-00081-7: SMD Chip Resistor, 392 Ohm, 1%, 100 mW, 0603 [1608 Metric], Thick Film, Precision; Temperature Coefficient: 100ppm/°C; Power: 100mW; Voltage Rating (DC): 50V; Voltage Rating: 75V
R35 = CMP-RES-00004-12: Resistor Thick Film 0603 100K Ohm 1% 1/10W 100ppm/C Molded SMD Punched Carrier T/R; Power: 100mW; Temperature Coefficient: 100ppm/°C; Voltage Rating: 75V
R36 R37 = CMP-RES-00082-7: Res Thin Film 0603 1M Ohm 0.1% 0.1W(1/10W) ±25ppm/C Pad SMD T/R; Temperature Coefficient: 25ppm/°C; Max Power Dissipation: 100mW; Voltage Rating: 75V
SJ1 = CMP-NOBOM-00017-1: Jumper that needs hand solder to close it.
U5 = CMP-OPTO-00002-4: OPTOISOLATOR 5KV TRIAC 6SMD
U6 = CMP-OPTO-00000-6: Optocoupler Ac-In 1-Ch Transistor Dc-Out 4-Pin Pdip Smd T/R
U7 = CMP-MCU-00001-3: MCU 32-Bit STM32 ARM Cortex-M0+ RISC 32KB Flash 2V to 3.6V 20-Pin TSSOP T/R
U8 = CMP-ICANA-00002-4: Op Amp Single Low Power Amplifier R-R I/O ±8V/16V 5-Pin SOT-23 T/R; Min Supply Voltage: 2.5V; Max Supply Voltage: 16V; Bandwidth: 5.5kHz
U9 = CMP-ICPWR-00007-4: 200mA positive 18VIN 3.3Vout SOT-23-5 Linear Voltage Regulators (LDO) ROHS; Max Supply Voltage: 18V; Output Voltage: 3.3V

## Sheet DebugProbe.SchDoc
size B; SheetNumber: 5; SheetTotal: 5; nhSheetName: DebugProbe
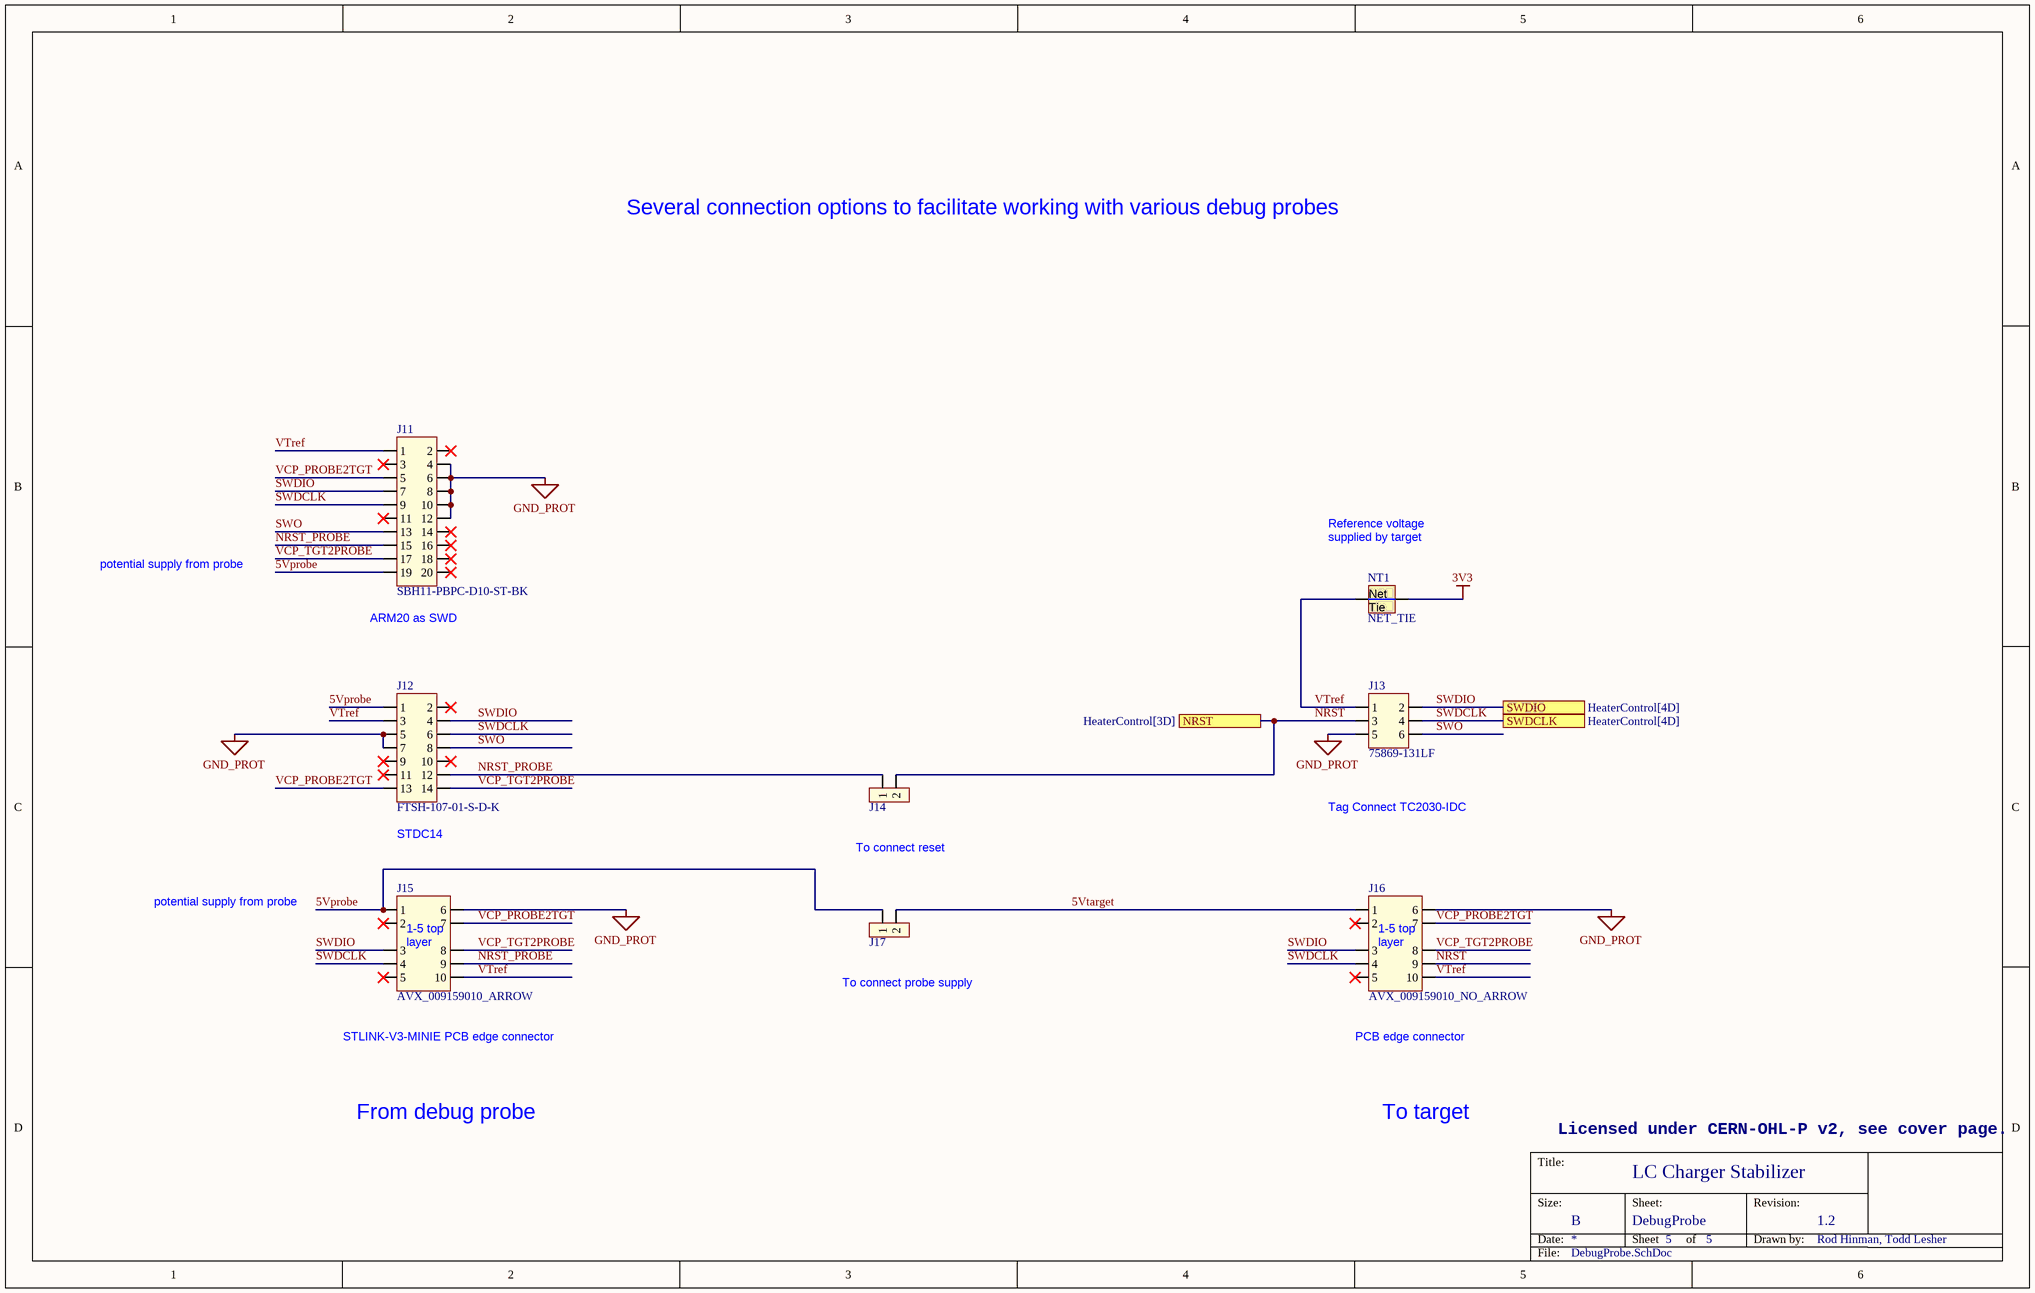
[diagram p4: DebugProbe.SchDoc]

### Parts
J11  SBH11-PBPC-D10-ST-BK  [SULLINS_SBH11-PBPC-D10-ST-BK]
J12  FTSH-107-01-S-D-K  [SAMTEC_FTSH-107-01-x-D-K]
J13  75869-131LF  [AMPHENOL_75869-131LF]
J14  61300211121  [61300211121]  (value not drawn)
J15  AVX_009159010_ARROW  [AVX_009159010_ARROW_NOSLOT]  (no BOM)
J16  AVX_009159010_NO_ARROW  [AVX_009159010_NO_ARROW_NOSLOT]  (no BOM)
J17  61300211121  [61300211121]  (value not drawn)
NT1  NET_TIE  [NETTIE_0.508mm_NOPADS]  (net tie, no BOM)

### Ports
NRST (see HeaterControl[3D]), SWDCLK (see HeaterControl[4D]), SWDIO (see HeaterControl[4D])

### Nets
3V3: NT1.2
GND_PROT: J11.4 J11.6 J11.8 J11.10 J11.12 J12.5 J12.7 J13.5 J15.6 J16.6
5Vprobe: J11.19 J12.1 J15.1 J17.1
5Vtarget: J16.1 J17.2
NRST: J13.3 J14.2 J16.9 ; port NRST
NRST_PROBE: J11.15 J12.12 J14.1 J15.9
SWDCLK: J11.9 J12.6 J13.4 J15.4 J16.4 ; port SWDCLK
SWDIO: J11.7 J12.4 J13.2 J15.3 J16.3 ; port SWDIO
SWO: J11.13 J12.8 J13.6
VCP_PROBE2TGT: J11.5 J12.13 J15.7 J16.7
VCP_TGT2PROBE: J11.17 J12.14 J15.8 J16.8
VTref: J11.1 J12.3 J13.1 J15.10 J16.10 NT1.1

Not connected (* = marked no-connect by the designer): J11 2* 3* 11* 14* 16* 18* 20*; J12 2* 9* 10* 11*; J15 2* 5*; J16 2* 5*

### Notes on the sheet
- Several connection options to facilitate working with various debug probes
- potential supply from probe
- supplied by target
- Reference voltage
- (near J11) ARM20 as SWD
- (near J12) STDC14
- Tag Connect TC2030-IDC
- To connect reset
- STLINK-V3-MINIE PCB edge connector
- To connect probe supply
- PCB edge connector
- From debug probe
- To target
- Licensed under CERN-OHL-P v2, see cover page.

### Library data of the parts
J11 = CMP-CONN-00034-2: Conn Shrouded Header (4 Sides) HDR 20 POS 2.54mm Solder ST Top Entry Thru-Hole; Number of Positions: 20
J12 = CMP-CONN-00033-4: Headers & Wire Housings High Reliability Header Strips, 0.050 pitch; Number of Contacts: 14
J13 = CMP-CONN-00036-3: 2x3 0.100" pitch through-hole vertical header shrouded
J14 J17 = CMP-CONN-00022-4: THT Vertical Pin Header WR-PHD, Pitch 2.54 mm, Single Row, 2 pins; Operating Supply Voltage: 250V; Contact Resistance: 20mR; Gender: Male; Pitch: 0.1inch; Number of Contacts: 2; Current Rating: 3A
J15 = CMP-NOBOM-00014-2: AVX 10-pin PCB edge connector, to connect to the arrow side of the connector.
J16 = CMP-NOBOM-00015-2: AVX 10-pin PCB edge connector, to connect to the arrow side of the connector.
NT1 = CMP-NOBOM-00011-1: Net tie with several footprints

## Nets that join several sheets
3V3: HeaterControl (9 pins), DebugProbe (NT1.2)
GND: PowerHV (5 pins), HeaterControl (J9.1 J9.2)
GND_PROT: Protect (36 pins), HeaterControl (13 pins), DebugProbe (10 pins)
Vcc_prot: Protect (18 pins), HeaterControl (C8.1 J10.2 U9.1 U9.3)
Vcoil: PowerHV (K1.PLUS), Protect (11 pins)
L2: PowerHV (J3.1 J3.2 L2.2 RV2.1), HeaterControl (J1.1 J1.2 R1.1)
LINE: PowerHV (6 pins), Protect (C5.1 R2.1 R3.1 R10.1)
NEUT: PowerHV (7 pins), Protect (D6.AC2), HeaterControl (C2.2 Q4.COM R33.2 U6.2)
NRST: HeaterControl (P1.3 SJ1.1), DebugProbe (J13.3 J14.2 J16.9)
PROT_RESET: PowerHV (K1.RESET), Protect (D1.A Q2.3)
PROT_SET: PowerHV (K1.SET), Protect (D2.A Q3.3)
sense_prot: Protect (8 pins), HeaterControl (R36.1)
SWDCLK: HeaterControl (P1.4 U7.19), DebugProbe (5 pins)
SWDIO: HeaterControl (P1.2 U7.18), DebugProbe (5 pins)

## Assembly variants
As Built: not fitted C1 MECH1 R23 R28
